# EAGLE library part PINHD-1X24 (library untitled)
PIN HEADER
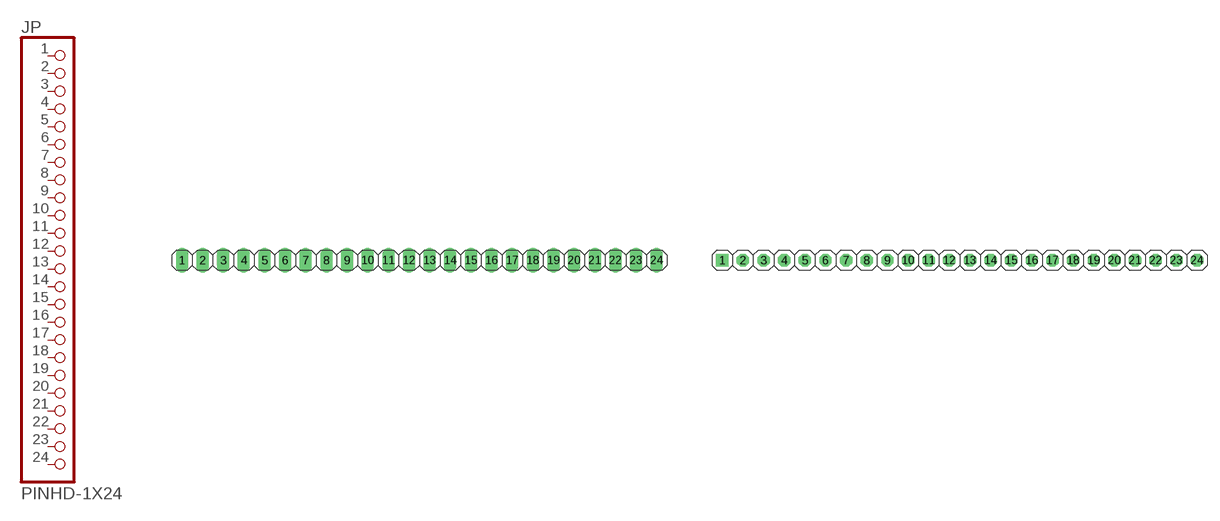
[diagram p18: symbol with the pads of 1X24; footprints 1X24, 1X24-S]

Designator prefix JP

## PINHD-1X24_2.54  [1X24]
1  1  pas
2  2  pas
3  3  pas
4  4  pas
5  5  pas
6  6  pas
7  7  pas
8  8  pas
9  9  pas
10  10  pas
11  11  pas
12  12  pas
13  13  pas
14  14  pas
15  15  pas
16  16  pas
17  17  pas
18  18  pas
19  19  pas
20  20  pas
21  21  pas
22  22  pas
23  23  pas
24  24  pas

## PINHD-1X24_2.54-S  [1X24-S]
Pads as for 1X24

## PINHD-1X24_2.00  [1X24M]
Pads as for 1X24

## PINHD-1X24_2.54-90°  [1X24/90]
Pads as for 1X24

## PINHD-1X24_2.54-90°-S  [1X24/90-S]
Pads as for 1X24

## PINHD-1X24_2.54-SMD  [1X24SMD]
Pads as for 1X24

## PINHD-1X24_2.54-SMD-90°  [1X24SMD/90]
Pads as for 1X24

## Footprint 1X24 (pad centres in mm)
PIN HEADER - 2.54
drill 1.016 long: 1 -29.21,0; 2 -26.67,0; 3 -24.13,0; 4 -21.59,0; 5 -19.05,0; 6 -16.51,0; 7 -13.97,0; 8 -11.43,0; 9 -8.89,0; 10 -6.35,0; 11 -3.81,0; 12 -1.27,0; 13 1.27,0; 14 3.81,0; 15 6.35,0; 16 8.89,0; 17 11.43,0; 18 13.97,0; 19 16.51,0; 20 19.05,0; 21 21.59,0; 22 24.13,0; 23 26.67,0; 24 29.21,0

## Footprint 1X24-S (pad centres in mm)
PIN HEADER - 2.54
drill 1.016 square: 1 -29.21,0
drill 1.016 octagon: 2 -26.67,0; 3 -24.13,0; 4 -21.59,0; 5 -19.05,0; 6 -16.51,0; 7 -13.97,0; 8 -11.43,0; 9 -8.89,0; 10 -6.35,0; 11 -3.81,0; 12 -1.27,0; 13 1.27,0; 14 3.81,0; 15 6.35,0; 16 8.89,0; 17 11.43,0; 18 13.97,0; 19 16.51,0; 20 19.05,0; 21 21.59,0; 22 24.13,0; 23 26.67,0; 24 29.21,0

## Footprint 1X24M (pad centres in mm)
PIN HEADER - 2
drill 0.914 square: 1 -23,0
drill 0.914 round: 2 -21,0; 3 -19,0; 4 -17,0; 5 -15,0; 6 -13,0; 7 -11,0; 8 -9,0; 9 -7,0; 10 -5,0; 11 -3,0; 12 -1,0; 13 1,0; 14 3,0; 15 5,0; 16 7,0; 17 9,0; 18 11,0; 19 13,0; 20 15,0; 21 17,0; 22 19,0; 23 21,0; 24 23,0

## Footprint 1X24/90 (pad centres in mm)
PIN HEADER - 2.54 90°
drill 1.016 long: 1 -24.13,-3.81; 2 -21.59,-3.81; 3 -19.05,-3.81; 4 -16.51,-3.81; 5 -13.97,-3.81; 6 -11.43,-3.81; 7 -8.89,-3.81; 8 -6.35,-3.81; 9 -3.81,-3.81; 10 -1.27,-3.81; 11 1.27,-3.81; 12 3.81,-3.81; 13 6.35,-3.81; 14 8.89,-3.81; 15 11.43,-3.81; 16 13.97,-3.81; 17 16.51,-3.81; 18 19.05,-3.81; 19 21.59,-3.81; 20 24.13,-3.81; 21 26.67,-3.81; 22 29.21,-3.81; 23 31.75,-3.81; 24 34.29,-3.81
